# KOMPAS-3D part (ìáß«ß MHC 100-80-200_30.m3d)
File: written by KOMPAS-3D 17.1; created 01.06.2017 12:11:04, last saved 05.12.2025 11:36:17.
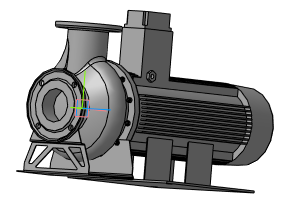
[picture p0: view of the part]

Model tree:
1. Операция без истории:4

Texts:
  ООО АДЛ ГРУПП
